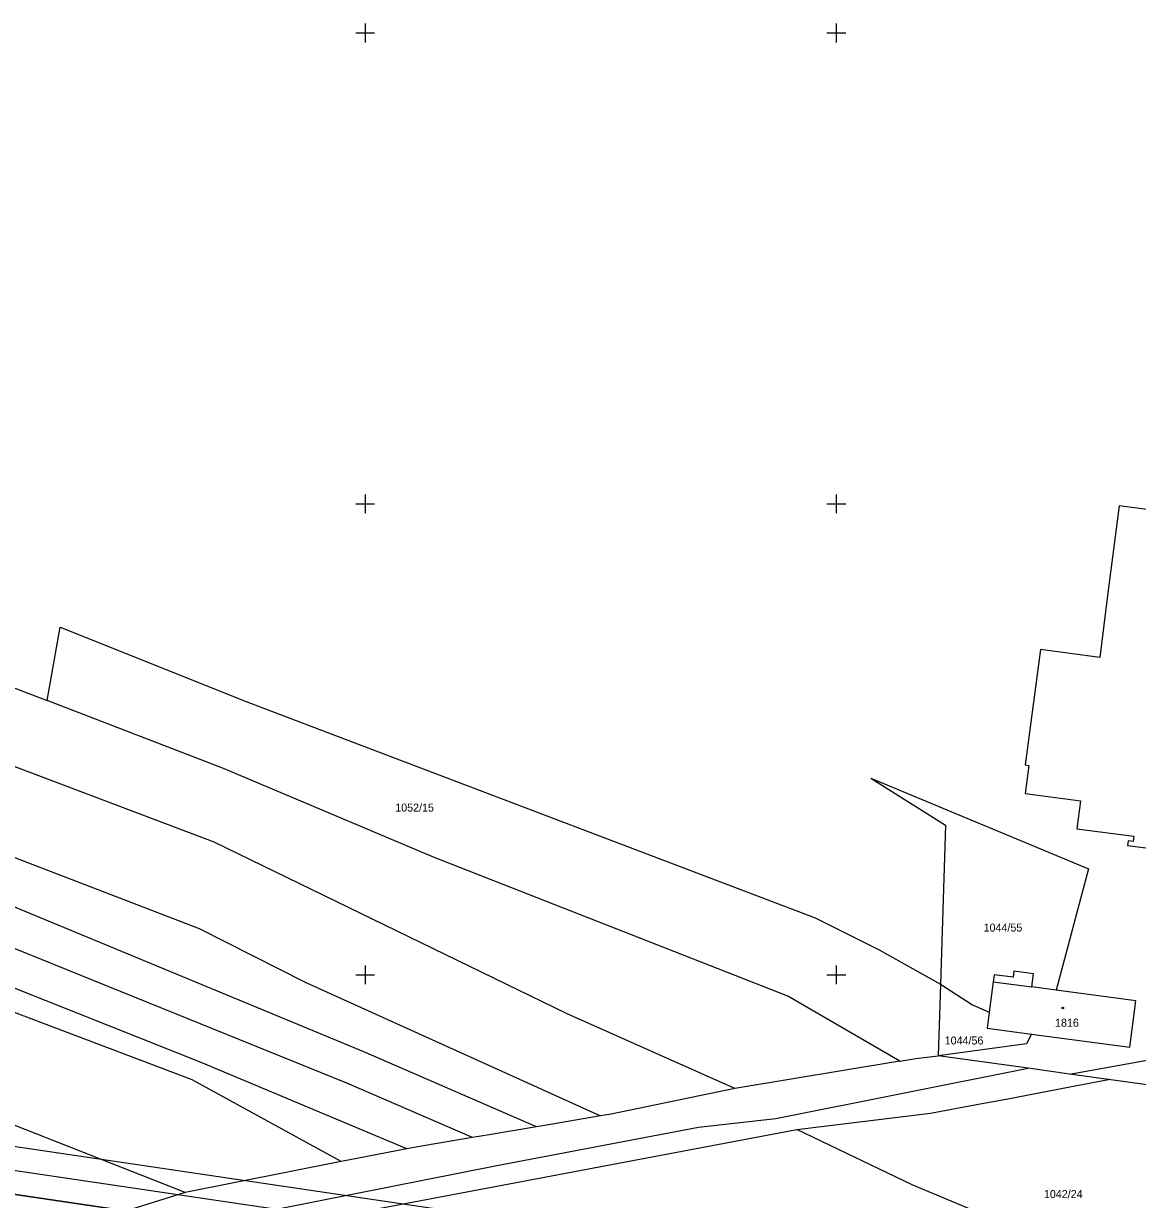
# Model space of a CAD drawing. Extents: x -779302 to -774398, y -1144902 to -1142831.
# Drawn here: x -775672.5 to -775436.1, y -1144247.7 to -1143998 of the extents above; entities that cross this region are included whole.
import ezdxf

# ---------------------------------------------------------------- set-up
doc = ezdxf.new("R2010")
doc.units = 0
for name, color, linetype in [('hektosit - Vrstva 5', 7, 'Continuous'), ('Hranice parcel', 7, 'Continuous'), ('Parcelní čísla', 7, 'Continuous'), ('Vnitřní kresba', 7, 'Continuous'), ('Vrstva 1', 7, 'Continuous'), ('Značky budov', 7, 'Continuous')]:
    doc.layers.add(name, color=color, linetype=linetype)

msp = doc.modelspace()

# ---------------------------------------------------------------- linework, layer by layer
at = {"layer": 'hektosit - Vrstva 5'}
for p, q in [((-775602, -1144000), (-775598, -1144000)), ((-775600, -1143998), (-775600, -1144002)), ((-775502, -1144000), (-775498, -1144000)), ((-775500, -1143998), (-775500, -1144002)), ((-775602, -1144100), (-775598, -1144100)), ((-775600, -1144098), (-775600, -1144102)), ((-775502, -1144100), (-775498, -1144100)), ((-775500, -1144098), (-775500, -1144102)), ((-775602, -1144200), (-775598, -1144200)), ((-775600, -1144198), (-775600, -1144202)), ((-775502, -1144200), (-775498, -1144200)), ((-775500, -1144198), (-775500, -1144202))]:
    msp.add_line(p, q, dxfattribs=at)
at = {"layer": 'Hranice parcel'}
for p, q in [((-775774.61, -1144100.46), (-775667.52, -1144141.78)), ((-775667.52, -1144141.78), (-775664.78, -1144126.16)), ((-775630.09, -1144156.22), (-775667.52, -1144141.78)), ((-775477.9, -1144202.01), (-775478.38, -1144217.19)), ((-775450.52, -1144221.07), (-775411.43, -1144214.05)), ((-775483.1, -1144217.76), (-775478.38, -1144217.19)), ((-775459.3, -1144219.85), (-775478.38, -1144217.19)), ((-775486.51, -1144218.32), (-775521.56, -1144224.12)), ((-775486.51, -1144218.32), (-775483.1, -1144217.76)), ((-775450.52, -1144221.07), (-775459.3, -1144219.85)), ((-775442.24, -1144222.22), (-775450.52, -1144221.07)), ((-775398.7, -1144228.28), (-775442.24, -1144222.22)), ((-775605.08, -1144239.64), (-775638.22, -1144246.24)), ((-775638.22, -1144246.24), (-775703.79, -1144266.62))]:
    msp.add_line(p, q, dxfattribs=at)
for points in [[(-775521.56, -1144224.12), (-775557.12, -1144208.3), (-775632.07, -1144171.85), (-775769.17, -1144119.97), (-775885.87, -1144076.77)], [(-775892.78, -1144091.09), (-775635.24, -1144190.2), (-775612.76, -1144201.57), (-775550.02, -1144229.95)], [(-775563.63, -1144232.28), (-775600.26, -1144216.37), (-775699.57, -1144175.22), (-775895.81, -1144097.04)], [(-775403.91, -1144105.14), (-775439.96, -1144100.43), (-775442.39, -1144118.91), (-775444.09, -1144132.61), (-775456.67, -1144130.95), (-775459.92, -1144155.45), (-775459.13, -1144155.55), (-775459.91, -1144161.47), (-775457.74, -1144161.76), (-775448.16, -1144163.03), (-775448.95, -1144168.98), (-775436.84, -1144170.56), (-775436.99, -1144171.67), (-775438.02, -1144171.54), (-775438.15, -1144172.51), (-775424.21, -1144174.33)], [(-775577.24, -1144234.58), (-775603.93, -1144223.03), (-775702.67, -1144183.02), (-775899.59, -1144104.7)], [(-775591.14, -1144236.99), (-775634.82, -1144218.59), (-775714.21, -1144187.09), (-775903.4, -1144112.88)], [(-775605.08, -1144239.64), (-775636.76, -1144222.34), (-775699.39, -1144198.57), (-775748.77, -1144179.7), (-775783.38, -1144167.15), (-775829.32, -1144150.55), (-775907.32, -1144121.53)], [(-775664.78, -1144126.16), (-775624.92, -1144142.09), (-775504.49, -1144187.88), (-775490.89, -1144194.72), (-775477.9, -1144202.01)], [(-775638.22, -1144246.24), (-775710.57, -1144217.77), (-775771.68, -1144193.36), (-775914.52, -1144137.68)], [(-775486.51, -1144218.32), (-775510.26, -1144204.53), (-775585.52, -1144174.99), (-775630.09, -1144156.22)], [(-775492.68, -1144158.24), (-775446.49, -1144177.53), (-775453.3, -1144203.26)], [(-775492.68, -1144158.24), (-775476.82, -1144168.24), (-775477.9, -1144202.01)], [(-775453.3, -1144203.26), (-775458.47, -1144202.56), (-775458.11, -1144199.77), (-775462.29, -1144199.23), (-775462.46, -1144200.53), (-775466.5, -1144200), (-775466.69, -1144201.49), (-775467.53, -1144207.97)], [(-775477.9, -1144202.01), (-775471.09, -1144206.35), (-775467.53, -1144207.97)], [(-775458.55, -1144212.59), (-775437.71, -1144215.38), (-775436.39, -1144205.54), (-775453.3, -1144203.26)], [(-775467.53, -1144207.97), (-775467.97, -1144211.33), (-775458.55, -1144212.59)], [(-775458.55, -1144212.59), (-775459.65, -1144214.64), (-775478.38, -1144217.19)], [(-775854.19, -1144322.57), (-775847.52, -1144320.58), (-775788.13, -1144302.89), (-775641, -1144254.13), (-775572.06, -1144240.51), (-775529.27, -1144232.36), (-775512.82, -1144230.54), (-775459.3, -1144219.85)], [(-775508.4, -1144232.87), (-775479.98, -1144229.35), (-775469.43, -1144227.4), (-775463.95, -1144226.39), (-775450.4, -1144223.79), (-775442.24, -1144222.22)], [(-775521.56, -1144224.12), (-775547.79, -1144229.57), (-775550.02, -1144229.95)], [(-775550.02, -1144229.95), (-775560.27, -1144231.71), (-775563.63, -1144232.28)], [(-775563.63, -1144232.28), (-775573.68, -1144233.98), (-775577.24, -1144234.58)], [(-775607.93, -1144251.93), (-775606.17, -1144251.3), (-775508.4, -1144232.87)], [(-775577.24, -1144234.58), (-775588.03, -1144236.41), (-775591.14, -1144236.99)], [(-775405.59, -1144277.47), (-775483.88, -1144244.62), (-775508.4, -1144232.87)], [(-775591.14, -1144236.99), (-775601.8, -1144238.99), (-775605.08, -1144239.64)]]:
    msp.add_lwpolyline(points, dxfattribs=at)
at = {"layer": 'Vnitřní kresba'}
msp.add_line((-775466.69, -1144201.49), (-775458.47, -1144202.56), dxfattribs=at)
at = {"layer": 'Vrstva 1'}
for points in [[(-774799.29, -1144366.04), (-776045.7, -1144181.56), (-776089.18, -1144475.34), (-774842.77, -1144659.83)], [(-774846.98, -1144654.15), (-776083.5, -1144471.13), (-776041.48, -1144187.23), (-774804.97, -1144370.25)], [(-774810.64, -1144374.46), (-775834.48, -1144222.92), (-775875.04, -1144496.94), (-774851.19, -1144648.48)], [(-774851.19, -1144648.48), (-775875.04, -1144496.94), (-775834.48, -1144222.92), (-774810.64, -1144374.46)]]:
    msp.add_lwpolyline(points, close=True, dxfattribs=at)
at = {"layer": 'Značky budov'}
msp.add_circle((-775451.92, -1144207.05), 0.175, dxfattribs=at)

# ---------------------------------------------------------------- texts
at = {"layer": 'Parcelní čísla'}
for s, p in [('1052/15', (-775593.63, -1144165.35)), ('1044/55', (-775468.73, -1144190.82)), ('1816', (-775453.57, -1144211.03)), ('1044/56', (-775476.99, -1144214.8)), ('1042/24', (-775455.93, -1144247.41))]:
    msp.add_text(s, height=1.7, dxfattribs=at).set_placement(p)

doc.saveas('drawing.dxf')
